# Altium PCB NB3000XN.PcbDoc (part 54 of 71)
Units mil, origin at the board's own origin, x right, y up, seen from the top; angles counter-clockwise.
Board outline 9527.56 x 6929.77 mil, 6 copper layers (Top Layer, GND+SHIELD, MidLayer1, MidLayer2, P2 - 3V3+5V0, Bottom Layer), stack 62.375 mil thick; 832 components, 1027 nets, 4655 pads, 4981 vias.
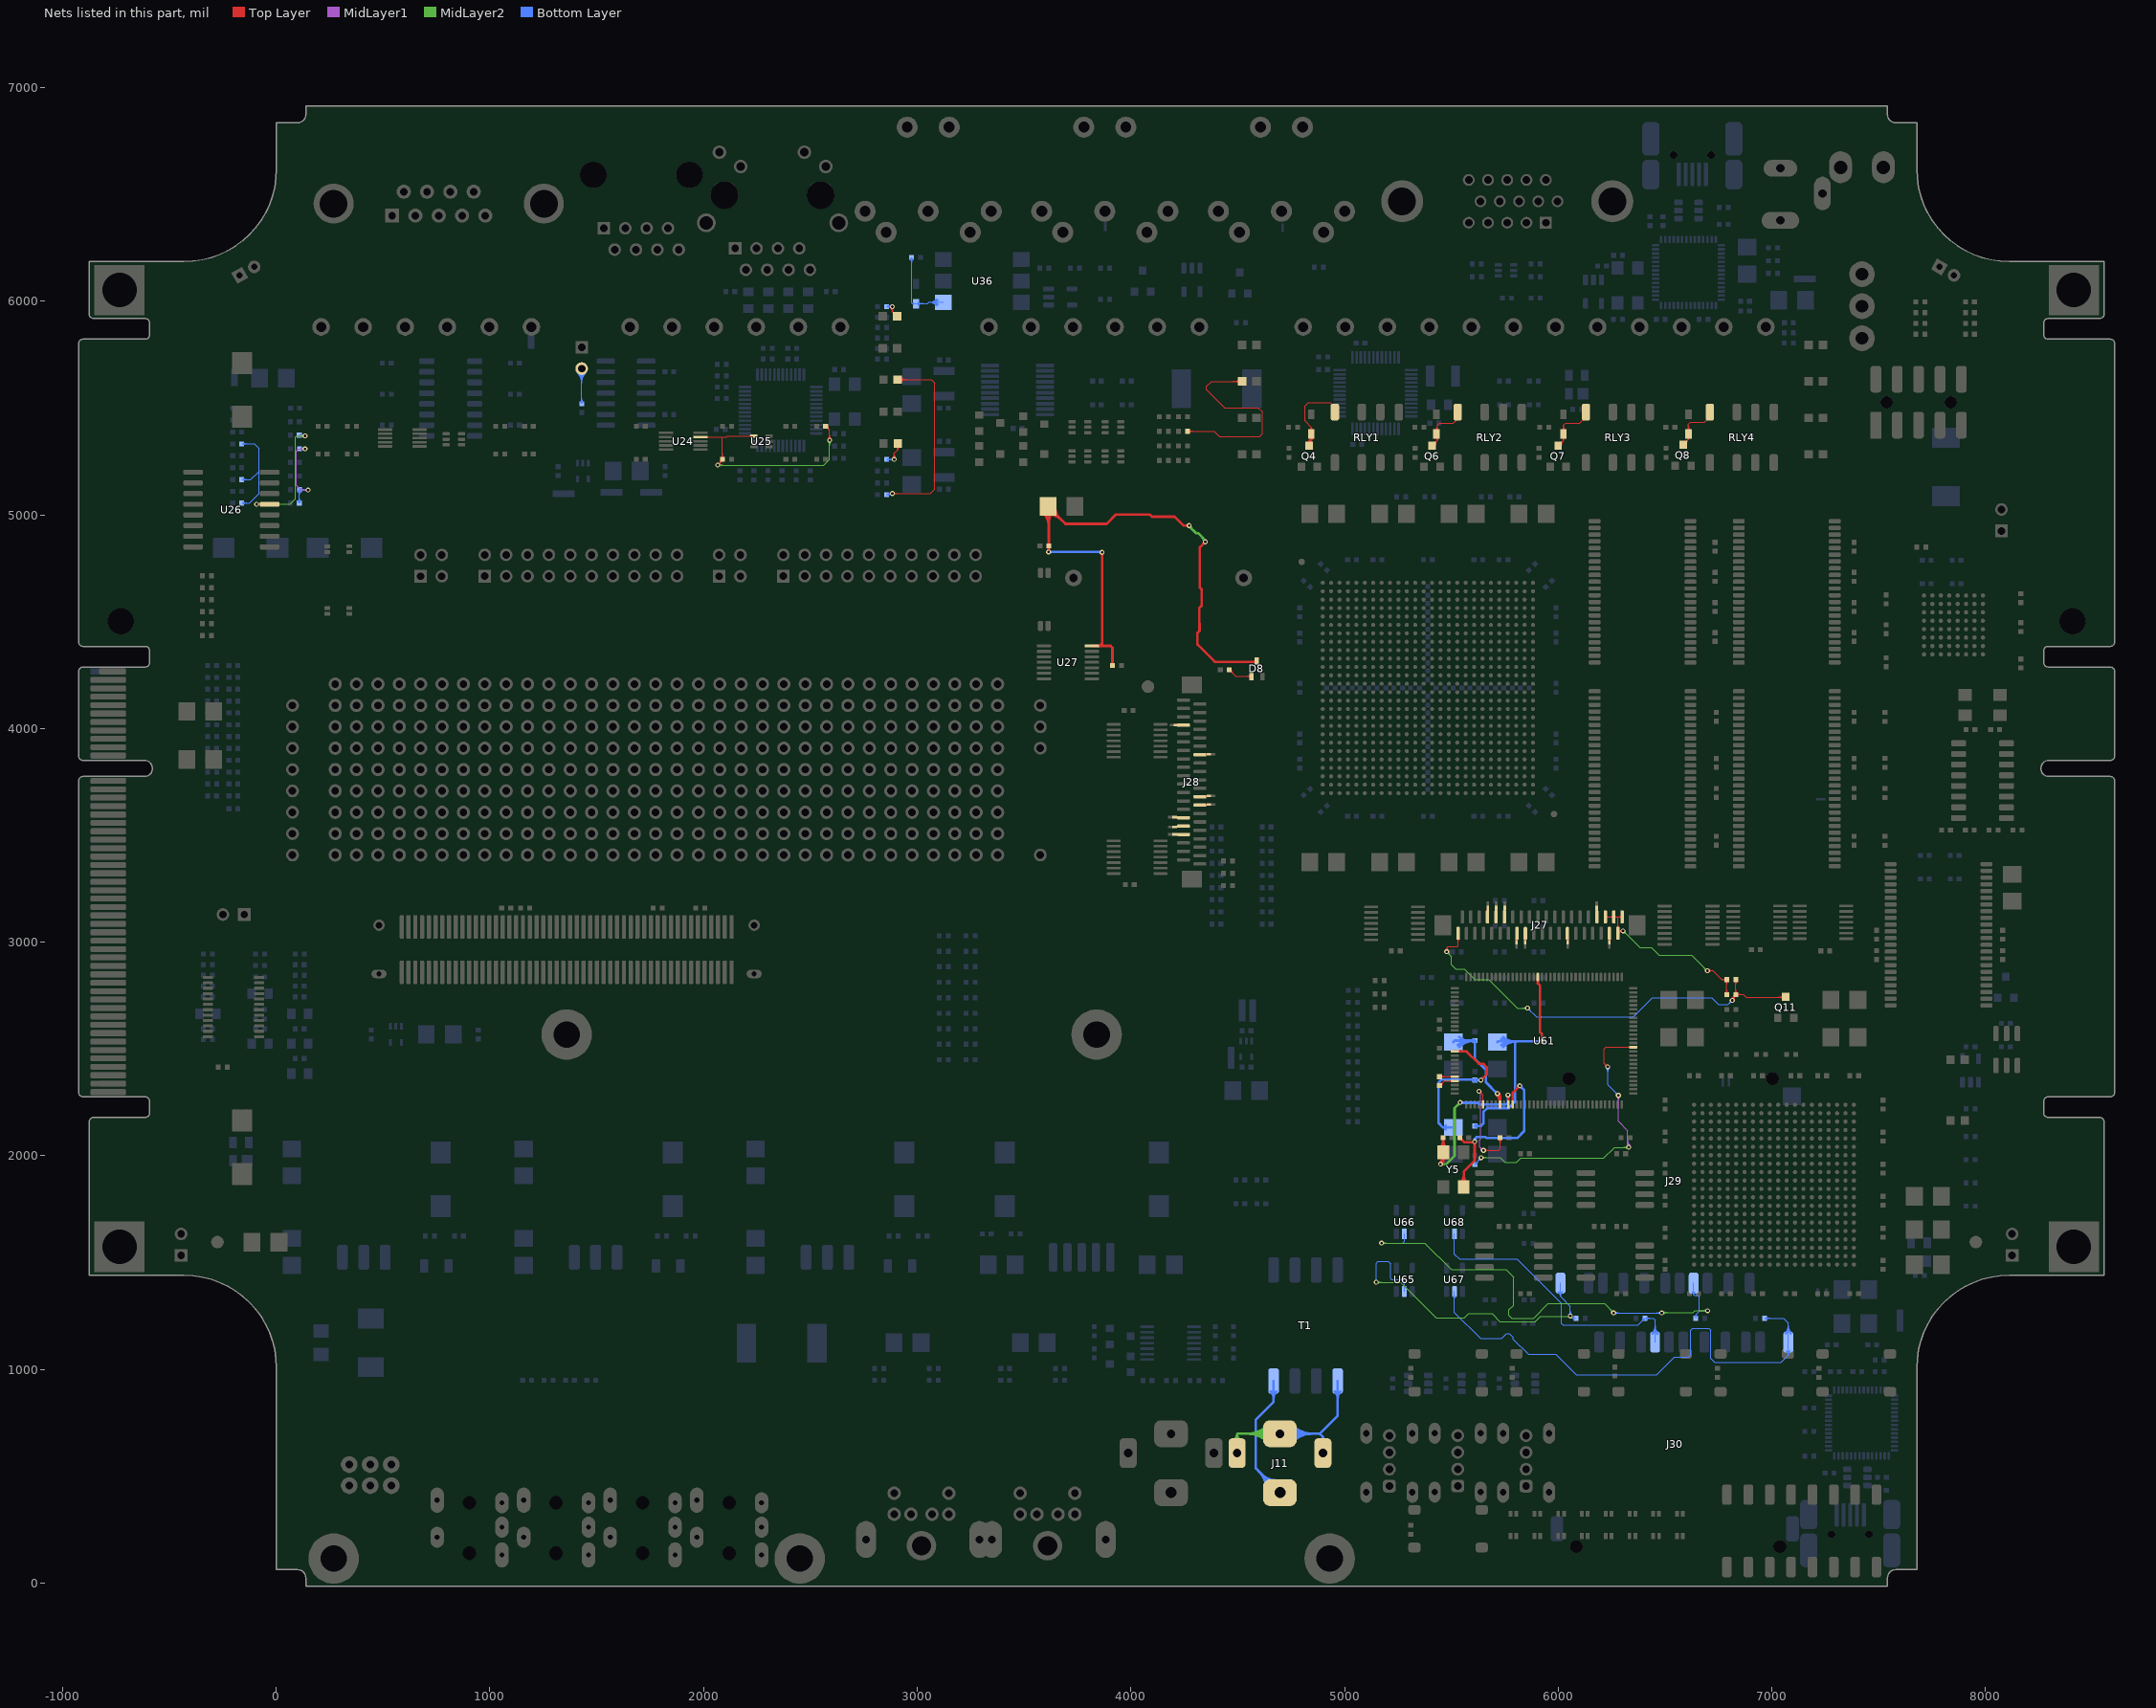
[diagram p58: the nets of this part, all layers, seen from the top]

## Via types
v1: diameter 23, hole 11.81, Top Layer to Bottom Layer, 3672 vias
v2: diameter 26, hole 11.81, Top Layer to Bottom Layer, 461 vias
v3: diameter 19, hole 11.81, Top Layer to Bottom Layer, tented both sides, 396 vias
v4: diameter 23.62, hole 11.81, Top Layer to Bottom Layer, 288 vias
v5: diameter 20, hole 11.81, Top Layer to Bottom Layer, 91 vias
v6: diameter 23, hole 11.81, Top Layer to Bottom Layer, tented both sides, 50 vias
v7: diameter 31, hole 11.81, Top Layer to Bottom Layer, 15 vias
v8: diameter 27.56, hole 11.81, Top Layer to Bottom Layer, tented both sides, 4 vias
v9: diameter 29, hole 11.81, Top Layer to Bottom Layer, 3 vias
v10: diameter 21, hole 11.81, Top Layer to Bottom Layer, 1 vias

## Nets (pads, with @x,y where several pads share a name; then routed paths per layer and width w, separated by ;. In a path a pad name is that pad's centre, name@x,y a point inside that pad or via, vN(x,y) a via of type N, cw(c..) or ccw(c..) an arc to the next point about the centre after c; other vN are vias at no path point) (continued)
NetC104_1: C104.1 R136.2 U24.4 U25.1 | length 1519
  Top Layer w4: U24.4@1985.71,5364.68 2089.69,5364.68 ; U24.4@2016,5361.86 cw(c2022.83,5355.03) 2022.83,5364.68 cw(c2022.83,5374.34) U24.4@2016,5367.51 ; v1(2066.19,5233.37) 2089.68,5256.87 R136.2@2089.68,5260 2087.19,5262.5 2087.19,5362.19 2089.69,5364.68 ; v1@2066.19,5238.87 ccw(c2066.19,5252.15) 2075.58,5242.76 ccw(c2084.97,5233.37) v1@2071.69,5233.37 ; v1@2066.19,5242.87 ccw(c2066.19,5265.81) 2082.41,5249.59 ccw(c2098.63,5233.37) v1@2075.69,5233.37 ; v1@2071.91,5239.1 ccw(c2051.5,5259.51) R136.2@2080.37,5259.51 ; 2078.28,5245.47 cw(c2089.68,5234.06) R136.2@2089.68,5250.19 ; 2078.74,5245.92 ccw(c2065.16,5259.51) R136.2@2084.37,5259.51 ; R136.2@2083.1,5267.08 ccw(c2073.21,5276.96) 2087.19,5276.96 ; 2087.19,5279.36 ccw(c2108.55,5279.36) R136.2@2093.45,5264.25 ; 2087.19,5289.02 ccw(c2118.21,5289.02) R136.2@2096.27,5267.08 ; U25.1@2221.99,5365.85 ccw(c2211.96,5355.82) 2211.96,5370 ccw(c2211.96,5384.18) U25.1@2221.99,5374.15 ; U25.1@2235,5370 2112.17,5370 2106.86,5364.68 2089.69,5364.68 ; C104.1@2571.54,5405.19 cw(c2571.53,5381.5) 2588.28,5398.25 cw(c2605.03,5415) C104.1@2581.35,5415 ; C104.1@2571.54,5409.19 cw(c2571.53,5395.16) 2581.45,5405.08 cw(c2591.38,5415) C104.1@2577.35,5415 ; C104.1@2571.54,5415 2590.19,5396.34 v1(2590.19,5350.04) ; v1@2583.47,5356.76 ccw(c2567.26,5372.98) 2590.19,5372.98 ccw(c2613.13,5372.98) v1@2596.91,5356.76 ; v1@2586.3,5353.93 ccw(c2576.91,5363.32) 2590.19,5363.32 ccw(c2603.47,5363.32) v1@2594.08,5353.93
  MidLayer2 w4: v1(2066.19,5233.37) 2535,5233.37 2563.37,5233.37 2590.19,5260.19 v1(2590.19,5350.04) ; v1@2070.08,5229.49 cw(c2079.47,5220.1) 2079.47,5233.37 cw(c2079.47,5246.65) v1@2070.08,5237.26 ; v1@2072.91,5226.66 cw(c2089.13,5210.44) 2089.13,5233.37 cw(c2089.13,5256.31) v1@2072.91,5240.09 ; v1@2583.47,5343.32 cw(c2567.26,5327.11) 2590.19,5327.11 cw(c2613.13,5327.11) v1@2596.91,5343.32 ; v1@2586.3,5346.15 cw(c2576.91,5336.76) 2590.19,5336.76 cw(c2603.47,5336.76) v1@2594.08,5346.15
NetC108_1: C108.1 U26.13 | length 913.3
  Top Layer w4: v1(-91.81,5050.04) -76.48,5050.04 ; v1@-88.12,5050.04 cw(c-88.12,5026.22) U26.13@-71.27,5043.06 ; v1@-87.92,5050.04 ccw(c-87.92,5073.59) U26.13@-71.27,5056.94 ; -78.46,5050.04 cw(c-78.46,5035.87) U26.13@-68.44,5045.89 ; -78.26,5050.04 ccw(c-78.26,5063.93) U26.13@-68.44,5054.11 ; U26.13@-73.93,5052.03 cw(c-76.43,5052.56) -76.43,5050 ; U26.13@-73.91,5052.1 cw(c-76.48,5052.66) -76.48,5050.04 ; U26.13@-30.87,5050 -76.43,5050 ; -76.48,5050.04 cw(c-76.48,5047.44) -73.93,5047.98 ccw(c-76.43,5047.44) -76.43,5050 ; -76.48,5050.04 -76.43,5050
  MidLayer2 w4: v1(-91.81,5050.04) 65.19,5050.04 90.19,5075.04 90.19,5365 95.19,5370 v1(135,5370) v1@135,5370.15 ; v1@-87.92,5046.15 cw(c-78.53,5036.76) -78.53,5050.04 cw(c-78.53,5063.32) v1@-87.92,5053.93 ; v1@-85.09,5043.32 cw(c-68.87,5027.11) -68.87,5050.04 cw(c-68.87,5072.98) v1@-85.09,5056.76 ; v1@128.28,5363.28 ccw(c112.06,5347.06) 112.06,5370 ccw(c112.06,5392.93) v1@128.28,5376.72 ; v1@131.11,5366.11 ccw(c121.72,5356.72) 121.72,5370 ccw(c121.72,5383.28) v1@131.11,5373.89
  Bottom Layer w4: C108.1@112.24,5368.83 cw(c122.16,5358.91) 122.16,5372.94 cw(c122.16,5386.97) C108.1@112.24,5377.05 ; C108.1@115.07,5366 cw(c131.81,5349.25) 131.81,5372.94 cw(c131.81,5396.62) C108.1@115.07,5379.88 ; C108.1@116.77,5372.94 cw(c116.77,5354.53) v1@130.81,5366.44 ; C108.1@119.16,5372.94 ccw(c119.16,5385.84) v1@128.28,5376.72 ; v1@127.76,5363.85 ccw(c108.13,5347.2) C108.1@108.13,5372.94 132.06,5372.94 v1(135,5370) v1@135,5370.15
NetC109_2: C109.2 R143.2 R146.1 | length 799.1
  MidLayer1 w4: v1@128.28,5302.65 ccw(c112.06,5286.43) 112.06,5309.37 ccw(c112.06,5332.3) v1@128.28,5316.09 ; v1@131.11,5305.48 ccw(c121.72,5296.09) 121.72,5309.37 ccw(c121.72,5322.65) v1@131.11,5313.26 ; v1(135,5309.37) 104.37,5309.37 95,5300 95,5138.65 116.94,5116.71 v1(149.52,5116.71) v1@151.52,5116.71 ; v1@142.81,5109.99 ccw(c126.59,5093.77) 126.59,5116.71 ccw(c126.59,5139.64) v1@142.81,5123.43 ; v1@145.64,5112.82 ccw(c136.25,5103.43) 136.25,5116.71 ccw(c136.25,5129.99) v1@145.64,5120.6
  Bottom Layer w4: C109.2@101.19,5062.02 ccw(c84.44,5078.77) 108.13,5078.77 ccw(c131.81,5078.77) C109.2@115.07,5062.02 ; R143.2@102.05,5111.57 cw(c86.14,5095.66) 108.64,5095.66 cw(c131.14,5095.66) R143.2@115.23,5111.57 ; C109.2@104.02,5059.19 ccw(c94.1,5069.11) 108.13,5069.11 ccw(c122.16,5069.11) C109.2@112.24,5059.19 ; R143.2@104.88,5114.4 cw(c95.8,5105.32) 108.64,5105.32 cw(c121.48,5105.32) R143.2@112.4,5114.4 ; C109.2@108.13,5055.08 108.13,5083.37 108.64,5083.89 R143.2@108.64,5118.65 135.52,5118.65 137.47,5116.71 v1(149.52,5116.71) ; R146.1@108.64,5309.37 v1(135,5309.37) ; R143.2@112.4,5114.89 cw(c121.48,5105.81) 121.48,5118.65 cw(c121.48,5131.5) R143.2@112.4,5122.41 ; R146.1@112.4,5305.61 cw(c121.48,5296.53) 121.48,5309.37 cw(c121.48,5322.21) R146.1@112.4,5313.13 ; R143.2@115.23,5112.06 cw(c131.14,5096.16) 131.14,5118.65 cw(c131.14,5141.15) R143.2@115.23,5125.24 ; R146.1@115.23,5302.78 cw(c131.14,5286.87) 131.14,5309.37 cw(c131.14,5331.86) R146.1@115.23,5315.96 ; v1@128.28,5302.65 ccw(c112.06,5286.43) 112.06,5309.37 ccw(c112.06,5332.3) v1@128.28,5316.09 ; v1@131.11,5305.48 ccw(c121.72,5296.09) 121.72,5309.37 ccw(c121.72,5322.65) v1@131.11,5313.26
NetC110_1: C110.1 R144.2 R145.2 | length 666
  Bottom Layer w4: C110.1@-161.36,5055.08 -124.92,5055.08 -80.81,5099.19 -80.81,5204.19 ; R145.2@-160.85,5165.08 -119.92,5165.08 -80.81,5204.19 ; R144.2@-160.85,5332.58 -102.58,5332.58 -80.81,5310.81 -80.81,5204.19 ; C110.1@-157.25,5050.97 cw(c-147.33,5041.05) -147.33,5055.08 cw(c-147.33,5069.11) C110.1@-157.25,5059.19 ; R145.2@-157.09,5161.32 cw(c-148.01,5152.24) -148.01,5165.08 cw(c-148.01,5177.92) R145.2@-157.09,5168.84 ; R144.2@-157.09,5328.82 cw(c-148.01,5319.74) -148.01,5332.58 cw(c-148.01,5345.42) R144.2@-157.09,5336.34 ; C110.1@-154.42,5048.14 cw(c-137.67,5031.4) -137.67,5055.08 cw(c-137.67,5078.77) C110.1@-154.42,5062.02 ; R145.2@-154.26,5158.49 cw(c-138.35,5142.58) -138.35,5165.08 cw(c-138.35,5187.58) R145.2@-154.26,5171.67 ; R144.2@-154.26,5325.99 cw(c-138.35,5310.08) -138.35,5332.58 cw(c-138.35,5355.08) R144.2@-154.26,5339.17
NetC115_1: C115.1 C116.1 D8.3 R148.1 U27.14 | length 3427.9
  Top Layer w4: C116.1@3615.19,4854.52 C116.1@3615.67,4855
  Top Layer w12: C115.1@3588.41,5012.47 cw(c3522.61,4946.66) 3615.67,4946.66 ; C115.1@3596.9,5020.95 cw(c3551.58,4975.63) 3615.67,4975.63 ; v1@3611.3,4830.6 ccw(c3600.76,4841.14) 3615.67,4841.14 ; C116.1@3611.56,4850.89 cw(c3601.64,4840.97) 3615.67,4840.97 cw(c3629.7,4840.97) C116.1@3619.78,4850.89 ; C116.1@3611.56,4859.11 ccw(c3601.64,4869.03) 3615.67,4869.03 ccw(c3629.7,4869.03) C116.1@3619.78,4859.11 ; C116.1@3612.01,4858.66 C116.1@3615.67,4855 ; C115.1@3612.01,5002.69 cw(c3612.01,4912.63) 3675.7,4976.31 ; C115.1@3612.01,5014.69 cw(c3612.01,4953.6) 3655.21,4996.8 ; C115.1@3612.01,5040 C115.1@3615.67,5036.34 ; v1@3615.67,4827.19 C116.1@3615.67,4855 ; 3615.67,4838.83 ccw(c3627.31,4838.83) v1@3619.08,4830.6 ; 3615.67,4964.34 cw(c3683.73,4964.34) C115.1@3635.6,5012.47 ; 3615.67,4993.31 cw(c3654.76,4993.31) C115.1@3627.12,5020.95 ; C115.1@3633.38,5036.06 ccw(c3675.47,5036.06) C115.1@3645.71,5006.3 ; C115.1@3645.38,5036.06 ccw(c3716.44,5036.06) 3666.19,4985.82 ; U27.14@3817.2,4386.77 3853.63,4386.77 ; U27.14@3843.78,4387.66 ccw(c3843.78,4413.59) 3862.11,4395.26 ; v1@3861.3,4821.15 cw(c3851.91,4811.76) 3865.19,4811.76 cw(c3878.47,4811.76) v1@3869.08,4821.15 ; v1(3865.19,4825.04) 3865.19,4398.33 3853.63,4386.77 ; R148.1@3910.06,4299.25 ccw(c3900.98,4308.33) 3913.82,4308.33 ccw(c3926.66,4308.33) R148.1@3917.58,4299.25 ; R148.1@3913.82,4295 3913.82,4378.77 3905.82,4386.77 3853.63,4386.77 ; v1@4268.97,4946.15 ccw(c4259.58,4936.76) 4259.58,4950.04 ccw(c4259.58,4963.32) v1@4268.97,4953.93 ; v1(4272.86,4950.04) 4246.67,4950.04 4205,4991.71 4099.14,4991.71 4089.03,5001.81 3930.28,5001.81 3886.96,4958.5 3693.51,4958.5 C115.1@3615.67,5036.34 ; v1@4343.02,4874.37 cw(c4329.75,4874.37) 4339.14,4864.99 cw(c4348.52,4855.6) v1@4348.52,4868.87 ; v1(4348.52,4874.37) 4323.02,4848.87 4323.02,4660.47 4331.5,4651.99 4331.5,4574.78 4320,4563.28 4320,4492.3 4321.5,4490.8 4321.5,4457.99 4312.02,4448.51 4312.02,4392.84 4392.65,4312.21 4586.78,4312.21 D8.3@4590,4315.43 ; 4572.57,4312.21 ccw(c4572.57,4332.87) D8.3@4587.17,4318.26 ; C116.1@3615.67,4855 C115.1@3615.67,5036.34
  MidLayer2 w12: v1(4272.86,4950.04) 4272.86,4946.8 4304.63,4915.02 4313.95,4915.02 4348.52,4880.45 v1(4348.52,4874.37) ; v1@4278.36,4950.04 ccw(c4299.46,4950.04) 4284.54,4935.12 ; 4334.84,4894.13 cw(c4315.09,4874.37) v1@4343.02,4874.37
  Bottom Layer w12: v1(3615.19,4826.71) v1@3863.52,4826.71 ; v1@3619.08,4822.82 cw(c3628.47,4813.43) 3628.47,4826.71 cw(c3628.47,4839.99) v1@3619.08,4830.6 ; 3847.89,4826.71 cw(c3847.89,4807.74) v1@3861.3,4821.15
NetC157_2: C157.2 U61.11 Y5.1 | length 1098.4
  Top Layer w12: v1@5445.64,1965.26 ccw(c5407.74,2003.16) Y5.1@5461.33,2003.16 ; Y5.1@5447.3,2035.7 ccw(c5413.42,2069.58) 5461.33,2069.58 ; v1(5449.52,1961.37) 5461.33,1973.18 ; Y5.1@5450.07,1994.96 cw(c5434.61,1973.17) 5461.33,1973.17 ; v1@5454.12,1956.78 ccw(c5436.71,1974.19) 5461.33,1974.19 ; C157.2@5457.22,2080.89 cw(c5447.3,2070.97) 5461.33,2070.97 cw(c5475.36,2070.97) C157.2@5465.44,2080.89 ; C157.2@5461.33,2075.23 ccw(c5517.23,2075.23) Y5.1@5477.7,2035.7 ; C157.2@5461.33,2085 5461.33,1973.18 ; Y5.1@5473.28,1993.9 ccw(c5485.29,1973.17) 5461.33,1973.17 ; v1@5761.11,2281.11 cw(c5747.26,2267.26) 5766.85,2267.26 ; v1(5765,2285) 5766.85,2283.15 U61.11@5766.85,2240
  MidLayer2 w12: v1(5449.52,1961.37) 5476.37,1961.37 5515.19,2000.19 5515.19,2223.71 v1(5541.52,2250.04) ; v1@5453.41,1957.49 cw(c5462.8,1948.1) 5462.8,1961.37 cw(c5462.8,1974.65) v1@5453.41,1965.26 ; v1@5536.02,2250.04 cw(c5522.75,2250.04) 5532.14,2240.65 cw(c5541.52,2231.26) v1@5541.52,2244.54
  Bottom Layer w12: v1(5541.52,2250.04) 5543.38,2248.19 5625,2248.19 5633.3,2239.89 5729.04,2239.89 5754.89,2239.89 5765,2250 v1(5765,2285) v1@5770.9,2285 ; v1@5545.41,2253.93 ccw(c5559.27,2267.79) 5559.27,2248.19 ; v1@5761.11,2281.11 cw(c5751.72,2271.72) 5765,2271.72 cw(c5778.28,2271.72) v1@5768.89,2281.11
NetC169_2: C169.2 U61.12 Y5.3 | length 1095.6
  Top Layer w12: C169.2@5539.33,2079.19 cw(c5539.33,2065.16) 5549.25,2075.08 cw(c5559.17,2085) C169.2@5545.14,2085 ; C169.2@5539.33,2085 5561.14,2063.19 5606,2063.19 v1(5609.19,2066.37) 5609.19,1977.37 5559.1,1927.29 5559.1,1855.1 Y5.3@5557.5,1853.5 ; Y5.3@5542.3,1872.7 ccw(c5501.73,1913.27) 5559.1,1913.27 ; 5559.1,1905.54 ccw(c5605.54,1905.54) Y5.3@5572.7,1872.7 ; v1@5605.3,2062.49 cw(c5595.91,2053.1) 5609.19,2053.1 cw(c5622.47,2053.1) v1@5613.08,2062.49 ; U61.12@5786.53,2240 5786.53,2273.8 5787.73,2275 5787.73,2295.92 v1(5820.19,2328.37) ; v1@5814.69,2328.37 cw(c5801.41,2328.37) 5810.8,2318.99 cw(c5820.19,2309.6) v1@5820.19,2322.87
  Bottom Layer w12: v1(5609.19,2066.37) 5609.19,2079.19 5618.21,2088.21 ; v1@5614.27,2068.48 cw(c5631.02,2075.39) 5618.21,2088.21 ; v1@5820.19,2322.87 cw(c5820.19,2309.6) 5829.58,2318.99 cw(c5838.97,2328.37) v1@5825.69,2328.37 ; v1@5826.63,2328.37 v1(5820.19,2328.37) 5840.69,2307.87 5840.69,2115.19 5808.87,2083.37 5664.26,2083.37 5659.43,2088.21 5618.21,2088.21
NetC186_1: C186.1 U61.124 | length 146.3
  Top Layer w4: C186.1@5445,2370.67 5473.52,2370.67 5473.57,2370.72 U61.124@5516.83,2370.72 ; C186.1@5449.11,2366.56 cw(c5459.03,2356.64) 5459.03,2370.67 cw(c5459.03,2384.7) C186.1@5449.11,2374.78 ; C186.1@5451.94,2363.73 cw(c5468.68,2346.98) 5468.68,2370.67 cw(c5468.69,2394.36) C186.1@5451.94,2377.61 ; U61.124@5500.81,2367.89 ccw(c5493.98,2361.06) 5493.98,2370.72 ccw(c5493.98,2380.37) U61.124@5500.81,2373.54
NetC186_2: C186.2 U61.125 | length 155.2
  Top Layer w4: C186.2@5445,2329.33 5466.7,2351.03 U61.125@5516.83,2351.03 ; C186.2@5445,2335.14 ccw(c5445,2349.17) 5454.92,2339.25 ccw(c5464.84,2329.33) C186.2@5450.81,2329.33 ; C186.2@5445,2339.14 ccw(c5445,2362.83) 5461.75,2346.08 ; C186.2@5454.81,2329.33 cw(c5478.5,2329.33) 5461.75,2346.08 ; U61.125@5500.81,2348.2 ccw(c5493.98,2341.37) 5493.98,2351.03 ccw(c5493.98,2360.69) U61.125@5500.81,2353.86
NetC187_1: C187.1 U61.5 | length 743.4
  Top Layer w4: v1@5629.18,2292.81 cw(c5629.18,2269.88) 5645.4,2286.09 cw(c5661.62,2302.31) v1@5638.68,2302.31 ; v1@5629.18,2296.81 cw(c5629.18,2283.53) 5638.57,2292.92 cw(c5647.96,2302.31) v1@5634.68,2302.31 ; v1(5629.18,2302.31) 5648.74,2282.75 U61.5@5648.74,2240 ; U61.5@5645.91,2256.02 ccw(c5639.08,2262.85) 5648.74,2262.85 ccw(c5658.4,2262.85) U61.5@5651.57,2256.02 ; v4(5650,2025) 5720,2025 5728.08,2033.08 C187.1@5728.08,2085 ; v4@5654.11,2020.89 cw(c5664.03,2010.97) 5664.03,2025 cw(c5664.03,2039.03) v4@5654.11,2029.11 ; v4@5656.94,2018.06 cw(c5673.69,2001.31) 5673.69,2025 cw(c5673.69,2048.69) v4@5656.94,2031.94 ; C187.1@5721.14,2078.06 cw(c5704.39,2061.31) 5728.08,2061.31 cw(c5751.76,2061.31) C187.1@5735.01,2078.06 ; C187.1@5723.97,2080.89 cw(c5714.05,2070.97) 5728.08,2070.97 cw(c5742.1,2070.97) C187.1@5732.18,2080.89
  MidLayer1 w4: v1(5629.18,2302.31) 5637.81,2293.68 5637.81,2078.74 5633.02,2073.96 5633.02,2041.98 v4(5650,2025) ; v4@5640.19,2025 ccw(c5616.5,2025) 5633.25,2041.75 ccw(c5650,2058.5) v4@5650,2034.81 ; v4@5644.19,2025 ccw(c5630.16,2025) 5640.08,2034.92 ccw(c5650,2044.84) v4@5650,2030.81
NetC336_1: C336.1 C340.1 U61.9 | length 763.6
  Top Layer w12: v1@5711.3,2287.82 cw(c5672.24,2248.76) U61.9@5727.48,2248.76 ; v1(5715.19,2291.71) 5727.48,2279.42 U61.9@5727.48,2240 ; v1@5719.79,2296.3 cw(c5701.21,2277.73) 5727.48,2277.73
  Bottom Layer w12: C340.1@5510,2532.99 5516.34,2539.33 C336.1@5610,2539.33 5610,2455.3 5661.69,2403.61 5661.69,2345.21 v1(5715.19,2291.71) ; C340.1@5529.05,2517.88 cw(c5580.83,2466.1) 5580.83,2539.33 ; C340.1@5537.53,2509.4 cw(c5609.8,2437.13) C336.1@5609.8,2539.33 ; C340.1@5537.53,2556.59 ccw(c5579.2,2598.25) 5579.2,2539.33 ; C336.1@5605.89,2543.44 cw(c5595.97,2553.36) 5595.97,2539.33 cw(c5595.97,2525.3) 5605.89,2535.22 cw(c5595.97,2525.3) 5610,2525.3 cw(c5624.03,2525.3) C336.1@5614.11,2535.22 ; v1@5709.69,2291.71 ccw(c5696.41,2291.71) 5705.8,2301.1 ccw(c5715.19,2310.49) v1@5715.19,2297.21
NetC337_1: C337.1 C341.1 U61.118 | length 839.3
  Top Layer w12: U61.118@5516.83,2488.83 5571.17,2488.83 5628.63,2431.37 5648.63,2431.37 5665.19,2414.81 5665.19,2381.37 v1(5638.19,2354.37) ; v1@5638.19,2359.87 ccw(c5638.19,2373.15) 5647.58,2363.76 ccw(c5656.97,2354.37) v1@5643.69,2354.37
  Bottom Layer w4: v1@5638.15,2354.33 v1(5638.19,2354.37)
  Bottom Layer w12: C341.1@5473.94,2123.95 ccw(c5462.01,2120.6) 5462.01,2132.99 ; C341.1@5473.94,2142.03 cw(c5462.01,2145.39) 5462.01,2132.99 ; C341.1@5510,2132.99 5462.01,2132.99 ; 5587.99,2357.64 cw(c5587.99,2332.32) C337.1@5605.89,2350.22 ; C337.1@5614.11,2350.22 cw(c5624.03,2340.3) 5624.03,2354.33 cw(c5624.03,2368.36) C337.1@5614.11,2358.44 ; 5624.81,2354.33 ccw(c5624.81,2367.76) v1@5634.3,2358.26 ; 5625.02,2354.33 cw(c5625.02,2341.2) v1@5634.3,2350.49 ; v1@5638.15,2354.33 C337.1@5610,2354.33 5606.69,2357.64 5454.49,2357.64 5440,2343.14 5440,2155 5462.01,2132.99
NetC338_1: C338.1 C342.1 U61.85 | length 1340
  Top Layer w12: U61.85@5904.65,2837.34 5904.65,2807.4 5915.19,2796.85 5915.19,2580 5923.52,2571.67 v1(5923.52,2535.71) ; v1@5919.64,2539.6 ccw(c5910.25,2548.99) 5923.52,2548.99 ccw(c5936.8,2548.99) v1@5927.41,2539.6
  Bottom Layer w12: C338.1@5610,2139.33 5637.14,2139.33 5650,2152.19 5650,2205 5668.89,2223.89 5768.89,2223.89 5797.69,2252.69 5797.69,2528.4 5805,2535.71 ; C338.1@5614.11,2135.22 cw(c5624.03,2125.3) 5624.03,2139.33 cw(c5624.03,2153.36) C338.1@5614.11,2143.44 ; C342.1@5715,2532.99 5717.72,2535.71 5805,2535.71 ; C342.1@5734.05,2548.1 ccw(c5763.97,2578.03) 5763.97,2535.71 ; C342.1@5734.18,2518.01 cw(c5776.38,2476.54) 5776.38,2535.71 ; C342.1@5742.53,2556.59 ccw(c5792.94,2607) 5792.94,2535.71 ; C342.1@5742.74,2509.6 cw(c5805,2448.42) 5805,2535.71 ; v1@5919.64,2531.82 ccw(c5910.25,2522.43) 5910.25,2535.71 ccw(c5910.25,2548.99) v1@5919.64,2539.6 ; v1(5923.52,2535.71) 5805,2535.71
NetC339_1: C339.1 U61.50 | length 1969
  Top Layer w4: v1@6222.36,2416.71 ccw(c6199.42,2416.71) 6215.64,2432.93 ccw(c6231.86,2449.14) v1@6231.86,2426.21 ; v1@6226.36,2416.71 ccw(c6213.08,2416.71) 6222.47,2426.1 ccw(c6231.86,2435.49) v1@6231.86,2422.21 ; v1(6231.86,2416.71) 6215.19,2433.37 6215.19,2500.04 6223.66,2508.51 U61.50@6351.93,2508.51 ; U61.50@6335.91,2505.68 ccw(c6329.08,2498.85) 6329.08,2508.51 ccw(c6329.08,2518.17) U61.50@6335.91,2511.34
  MidLayer1 w4: v1@6275.14,2276.66 cw(c6258.92,2260.44) 6281.86,2260.44 cw(c6304.79,2260.44) v1@6288.57,2276.66 ; v1@6277.97,2279.49 cw(c6268.58,2270.1) 6281.86,2270.1 cw(c6295.14,2270.1) v1@6285.75,2279.49 ; v1(6281.86,2283.37) 6281.86,2161.63 6325,2118.48 6325,2040 v4(6330,2040) ; v4@6323.06,2046.94 ccw(c6318.39,2051.61) 6325,2051.61 ; 6325,2056.44 ccw(c6346.44,2056.44) v4@6331.28,2041.28 ; 6325,2066.1 ccw(c6356.1,2066.1) v4@6334.11,2044.11 ; 6325,2075.76 ccw(c6365.76,2075.76) v4@6336.94,2046.94
  MidLayer2 w4: v1(5639.52,1991.71) 5729.23,1991.71 5750.4,1970.54 5805.77,1970.54 5825.23,1990 6213.23,1990 6263.23,2040 v4(6330,2040) ; v1@5643.41,1987.82 cw(c5652.8,1978.43) 5652.8,1991.71 cw(c5652.8,2004.99) v1@5643.41,1995.6 ; v1@5646.24,1984.99 cw(c5662.46,1968.77) 5662.46,1991.71 cw(c5662.46,2014.64) v1@5646.24,1998.43 ; v4@6323.06,2033.06 ccw(c6306.31,2016.31) 6306.31,2040 ccw(c6306.31,2063.69) v4@6323.06,2046.94 ; v4@6325.89,2035.89 ccw(c6315.97,2025.97) 6315.97,2040 ccw(c6315.97,2054.03) v4@6325.89,2044.11
  Bottom Layer w4: C339.1@5610,1959.33 v1@5639.52,1988.85 ; C339.1@5610,1965.14 ccw(c5610,1979.17) 5619.92,1969.25 ccw(c5629.84,1959.33) C339.1@5615.81,1959.33 ; C339.1@5610,1969.14 ccw(c5610,1992.83) 5626.75,1976.08 ; C339.1@5619.81,1959.33 cw(c5643.5,1959.33) 5626.75,1976.08 ; C339.1@5621.29,1970.62 ccw(c5600.2,1991.71) v1@5630.02,1991.71 ; 5628.12,1977.45 ccw(c5613.86,1991.71) v1@5634.02,1991.71 ; 5628.18,1977.51 cw(c5639.52,1966.16) v1@5639.52,1982.21 ; v1@6225.14,2409.99 cw(c6208.92,2393.77) 6231.86,2393.77 cw(c6254.79,2393.77) v1@6238.57,2409.99 ; v1@6227.97,2412.82 cw(c6218.58,2403.43) 6231.86,2403.43 cw(c6245.14,2403.43) v1@6235.75,2412.82 ; v1(6231.86,2416.71) 6231.86,2333.37 v1(6281.86,2283.37) ; v1@6272.36,2283.37 ccw(c6249.42,2283.37) 6265.64,2299.59 ccw(c6281.86,2315.81) v1@6281.86,2292.87 ; v1@6276.36,2283.37 ccw(c6263.08,2283.37) 6272.47,2292.76 ccw(c6281.86,2302.15) v1@6281.86,2288.87
NetD3_1: D3.1 Q4.2 RLY1.8 | length 744
  Top Layer w4: Q4.2@4825.18,5337.46 ccw(c4792.13,5378.74) D3.1@4845,5378.74 ; Q4.2@4827.68,5334.34 ccw(c4798.79,5370.41) D3.1@4845,5370.41 ; Q4.2@4830.18,5331.22 ccw(c4805.46,5362.08) D3.1@4845,5362.08 ; Q4.2@4832.68,5328.1 ccw(c4812.13,5353.75) 4845,5353.75 ; Q4.2@4835,5324.21 4845,5334.21 D3.1@4845,5378.74 ; Q4.2@4835.18,5324.98 ccw(c4818.8,5345.43) 4845,5345.43 ; D3.1@4835.81,5362.05 cw(c4813.62,5339.85) 4845,5339.85 cw(c4876.39,5339.85) D3.1@4854.19,5362.05 ; D3.1@4837.92,5397.14 ccw(c4829.44,5410.19) 4845,5410.19 ; D3.1@4838.64,5364.88 cw(c4823.27,5349.51) 4845,5349.51 cw(c4866.73,5349.51) D3.1@4851.36,5364.88 ; D3.1@4840.1,5393.79 ccw(c4834.23,5402.82) 4845,5402.82 ccw(c4855.77,5402.82) D3.1@4849.9,5393.79 ; D3.1@4852.08,5397.14 cw(c4860.56,5410.19) 4845,5410.19 ; 4937.64,5522.36 cw(c4925.38,5510.11) RLY1.8@4941.93,5504.97 ; 4939.47,5520.53 ccw(c4953.86,5534.91) RLY1.8@4954.54,5514.58 ; RLY1.8@4942.32,5517.68 cw(c4932.53,5507.89) RLY1.8@4945.75,5503.78 ; RLY1.8@4955,5481.22 4955,5505 4935,5525 4830,5525 4815,5510 4815,5440.19 4845,5410.19 ; D3.1@4845,5378.74 4845,5410.19
NetD4_1: D4.1 Q6.2 RLY2.8 | length 455.9
  Top Layer w4: Q6.2@5410.51,5324.72 5435,5349.21 ; Q6.2@5410.76,5332.88 ccw(c5412.27,5348.05) Q6.2@5423.05,5337.27 ; Q6.2@5411.16,5336.86 ccw(c5413.35,5358.91) 5429.03,5343.24 ; Q6.2@5411.56,5340.84 ccw(c5414.43,5369.78) 5435,5349.21 ; Q6.2@5421.71,5325.58 cw(c5444.83,5326.33) 5428.47,5342.69 ; D4.1@5422.76,5397.03 ccw(c5407.35,5420) 5435,5420 ; D4.1@5424.99,5393.71 ccw(c5412.38,5412.5) 5435,5412.5 ; Q6.2@5425.71,5325.71 cw(c5457.47,5326.74) 5435,5349.21 ; D4.1@5427.1,5358.57 cw(c5424.83,5348.65) 5435,5348.65 ; D4.1@5427.21,5390.39 ccw(c5417.41,5404.99) 5435,5404.99 ; D4.1@5427.99,5362.47 cw(c5425.98,5353.67) 5435,5353.67 ; 5435,5351.93 cw(c5449.31,5351.93) D4.1@5439.19,5362.05 ; D4.1@5435,5370 5435,5349.21 ; D4.1@5435,5373.74 5435,5420 ; 5435,5405.55 ccw(c5449.31,5405.55) D4.1@5439.19,5395.43 ; RLY2.8@5535,5476.22 5535,5455 5510,5430 5445,5430 5435,5420
NetD5_1: D5.1 Q7.2 RLY3.8 | length 477.2
  Top Layer w4: Q7.2@6000.51,5324.72 6025,5349.21 ; Q7.2@6000.76,5332.88 ccw(c6002.27,5348.05) Q7.2@6013.05,5337.27 ; Q7.2@6001.16,5336.86 ccw(c6003.35,5358.91) 6019.03,5343.24 ; Q7.2@6001.56,5340.84 ccw(c6004.43,5369.78) 6025,5349.21 ; Q7.2@6011.71,5325.58 cw(c6034.83,5326.33) 6018.47,5342.69 ; Q7.2@6015.71,5325.71 cw(c6047.47,5326.74) 6025,5349.21 ; D5.1@6015.81,5395.43 ccw(c5993.62,5417.62) 6025,5417.62 ccw(c6056.39,5417.62) D5.1@6034.19,5395.43 ; D5.1@6018.64,5392.6 ccw(c6003.27,5407.97) 6025,5407.97 ccw(c6046.73,5407.97) D5.1@6031.36,5392.6 ; D5.1@6018.72,5359.86 cw(c6012.84,5349.21) 6025,5349.21 ; D5.1@6020.65,5363.36 cw(c6016.58,5355.99) 6025,5355.99 cw(c6033.42,5355.99) D5.1@6029.35,5363.36 ; D5.1@6025,5370 6025,5349.21 ; D5.1@6025,5373.74 6025,5420 6035,5430 6100,5430 6125,5455 RLY3.8@6125,5476.22 ; D5.1@6031.28,5359.86 ccw(c6037.16,5349.21) 6025,5349.21
  Top Layer w12: RLY3.8@6123.82,5475.04 RLY3.8@6130,5481.22
NetD6_1: D6.1 Q8.2 RLY4.8 | length 440.8
  Top Layer w4: Q8.2@6585,5329.21 Q8.2@6586.02,5329.21 ; Q8.2@6585.51,5329.72 6610,5354.21 ; Q8.2@6585.76,5337.88 ccw(c6587.27,5353.05) Q8.2@6598.05,5342.27 ; Q8.2@6586.16,5341.86 ccw(c6588.35,5363.91) 6604.03,5348.24 ; Q8.2@6586.56,5345.84 ccw(c6589.43,5374.78) 6610,5354.21 ; Q8.2@6596.71,5330.58 cw(c6619.83,5331.33) 6603.47,5347.69 ; Q8.2@6600.71,5330.71 cw(c6632.47,5331.74) 6610,5354.21 ; D6.1@6600.81,5395.43 ccw(c6578.62,5417.62) 6610,5417.62 ccw(c6641.39,5417.62) D6.1@6619.19,5395.43 ; D6.1@6603.64,5392.6 ccw(c6588.27,5407.97) 6610,5407.97 ccw(c6631.73,5407.97) D6.1@6616.36,5392.6 ; D6.1@6606.58,5358.7 cw(c6605.35,5354.21) 6610,5354.21 ; D6.1@6610,5375 6610,5354.21 ; D6.1@6610,5378.74 6610,5425 6620,5435 6685,5435 6710,5460 RLY4.8@6710,5481.22 ; D6.1@6613.43,5358.7 ccw(c6614.65,5354.21) 6610,5354.21
  Top Layer w12: RLY4.8@6707.85,5483.37 RLY4.8@6710,5481.22
NetD8_1: D8.1 R147.2 | length 201.7
  Top Layer w4: R147.2@4461.18,4265.19 cw(c4461.18,4241.5) 4477.93,4258.25 ; R147.2@4461.18,4269.19 cw(c4461.18,4255.16) R147.2@4471.1,4265.08 ; R147.2@4461.18,4275 4491.61,4244.57 D8.1@4564.41,4244.57 ; R147.2@4466.5,4274.51 ccw(c4478.15,4274.51) R147.2@4469.91,4266.27 ; R147.2@4470.5,4274.51 ccw(c4491.81,4274.51) 4476.74,4259.44 ; D8.1@4558.75,4238.91 ccw(c4545.1,4225.25) 4545.1,4244.57 ccw(c4545.1,4263.88) D8.1@4558.75,4250.22
NetD9_2: D9.2 R194.1 U36.1 | length 794.7
  Bottom Layer w4: R194.1@2967.23,6197.92 cw(c2951.32,6182.01) 2973.82,6182.01 cw(c2996.32,6182.01) R194.1@2980.41,6197.92 ; R194.1@2970.06,6200.75 cw(c2960.98,6191.67) 2973.82,6191.67 cw(c2986.66,6191.67) R194.1@2977.58,6200.75 ; R194.1@2973.82,6205 2973.82,5991.41 2976.49,5988.74 ; D9.2@2982.77,5984.33 ccw(c2976.49,5982.05) 2976.49,5988.74 ; D9.2@2982.77,5993.15 cw(c2976.49,5995.42) 2976.49,5988.74 ; D9.2@3001.36,5982.38 cw(c3016.73,5967.01) 3016.73,5988.74 cw(c3016.73,6010.47) D9.2@3001.36,5995.1 ; D9.2@3004.19,5979.55 cw(c3026.38,5957.36) 3026.38,5988.74 cw(c3026.39,6020.13) D9.2@3004.19,5997.93 ; U36.1@3090.33,5976.3 ccw(c3054.79,5951.87) 3054.79,5995 ; U36.1@3090.33,6013.69 cw(c3054.79,6038.13) 3054.79,5995 ; U36.1@3093.62,5978.57 ccw(c3062.39,5957.1) 3062.39,5995 ccw(c3062.39,6032.9) U36.1@3093.62,6011.43 ; U36.1@3096.92,5980.84 ccw(c3069.99,5962.33) 3069.99,5995 ccw(c3069.99,6027.67) U36.1@3096.92,6009.16 ; U36.1@3100.21,5983.1 ccw(c3077.6,5967.55) 3077.6,5995 ccw(c3077.6,6022.44) U36.1@3100.21,6006.9 ; U36.1@3122.52,5995 3054.78,5995 ; 2976.49,5988.74 D9.2@2995,5988.74 3048.52,5988.74 3054.78,5995
NetJ11_1: J11.1 T1.8 | length 1076
  Bottom Layer w12: 4597.03,524.75 cw(c4499.86,427.58) J11.1@4637.25,424.74 ; 4611.82,509.96 ccw(c4682.23,580.37) J11.1@4682.23,480.79 ; 4616.93,504.85 cw(c4538.85,426.78) J11.1@4649.25,424.49 ; 4632.31,489.47 ccw(c4682.23,539.4) J11.1@4682.23,468.79 ; 4636.83,484.95 cw(c4577.84,425.97) J11.1@4661.24,424.24 ; T1.8@4654.56,897.45 cw(c4622.13,865.01) 4668,865.01 cw(c4713.87,865.01) T1.8@4681.44,897.45 ; T1.8@4668,945.92 4668,848 4585,765 4585,536.78 J11.1@4697.98,423.8
NetJ11_2: J11.2 J11.3 J11.4 T1.5 | length 2056.1
  MidLayer2 w12: J11.3@4480.43,668.42 ccw(c4464.13,697.19) 4497.19,697.19 ; J11.3@4497.19,608.84 4497.19,697.19 ; J11.3@4513.95,668.42 cw(c4530.26,697.19) 4497.19,697.19 ; J11.4@4641.93,659.09 ccw(c4544.64,561.8) 4544.64,699.39 ccw(c4544.64,836.98) J11.4@4641.93,739.69 ; J11.4@4650.42,667.58 ccw(c4573.61,590.77) 4573.61,699.39 ccw(c4573.61,808.01) J11.4@4650.42,731.21 ; J11.4@4658.9,676.06 ccw(c4602.58,619.74) 4602.58,699.39 ccw(c4602.58,779.04) J11.4@4658.9,722.72 ; J11.4@4697.98,699.39 4499.39,699.39 4497.19,697.19
  Bottom Layer w12: J11.4@4697.98,699.39 4884.39,699.39 ; J11.4@4737.06,676.06 cw(c4793.38,619.74) 4793.38,699.39 cw(c4793.38,779.04) J11.4@4737.06,722.72 ; J11.4@4745.54,667.58 cw(c4822.35,590.77) 4822.35,699.39 cw(c4822.35,808.01) J11.4@4745.54,731.21 ; J11.4@4754.03,659.09 cw(c4851.32,561.8) 4851.32,699.39 cw(c4851.32,836.98) J11.4@4754.03,739.69 ; J11.2@4888.67,671.31 ccw(c4884.41,685.02) 4898.77,685.02 ; J11.2@4898.77,608.84 4898.77,685.02 ; J11.2@4908.86,671.31 cw(c4913.12,685.02) 4898.77,685.02 ; T1.5@4954.56,897.45 cw(c4922.13,865.01) 4968,865.01 cw(c5013.87,865.01) T1.5@4981.44,897.45 ; T1.5@4968,945.92 4968,783 4884.39,699.39 ; 4884.39,699.39 4898.77,685.02
NetJ26_2: J26.2 R212.2 | length 545.6
  Bottom Layer w4: J26.2@1410.24,5665.16 cw(c1363.25,5618.16) 1429.71,5618.16 cw(c1496.16,5618.17) J26.2@1449.17,5665.16 ; J26.2@1413.07,5667.99 cw(c1372.91,5627.82) 1429.71,5627.82 cw(c1486.51,5627.82) J26.2@1446.35,5667.99 ; J26.2@1415.9,5670.81 cw(c1382.56,5637.48) 1429.71,5637.48 cw(c1476.85,5637.48) J26.2@1443.52,5670.81 ; J26.2@1418.73,5673.64 cw(c1392.22,5647.13) 1429.71,5647.13 cw(c1467.19,5647.14) J26.2@1440.69,5673.64 ; R212.2@1423.41,5527.77 ccw(c1407.5,5543.68) 1430,5543.68 ccw(c1452.5,5543.68) R212.2@1436.59,5527.77 ; R212.2@1426.24,5524.94 ccw(c1417.16,5534.02) 1430,5534.02 ccw(c1442.84,5534.02) R212.2@1433.76,5524.94 ; J26.2@1429.71,5684.62 1429.71,5600.33 1430,5600.04 R212.2@1430,5521.18
NetJ27_1: J27.1 J27.2 J27.3 J27.5 R100.1 R101.1 | length 1338.2
  Top Layer w4: J27.5@6220.54,3118.39 J27.3@6259.91,3118.39 6280,3118.39 ; J27.5@6224.69,3114.23 cw(c6234.72,3104.2) 6234.72,3118.39 cw(c6234.72,3132.57) J27.5@6224.69,3122.54 ; J27.3@6255.75,3114.23 ccw(c6245.73,3104.2) 6245.73,3118.39 ccw(c6245.73,3132.57) J27.3@6255.75,3122.54 ; J27.3@6264.06,3114.23 cw(c6274.09,3104.2) 6274.09,3118.39 cw(c6274.09,3132.57) J27.3@6264.06,3122.54 ; J27.2@6275.44,3067.89 ccw(c6265.41,3077.92) 6279.59,3077.92 ccw(c6293.77,3077.92) J27.2@6283.75,3067.89 ; J27.2@6278.56,3040.58 cw(c6297,3022.14) v1@6302.39,3047.66 ; J27.2@6283.78,3045.8 cw(c6298.82,3030.76) v1@6303.21,3051.57 ; 6289,3051.02 cw(c6300.64,3039.37) v1@6304.04,3055.49 ; J27.1@6295.12,3114.23 ccw(c6285.1,3104.2) 6285.1,3118.39 ccw(c6285.1,3132.57) J27.1@6295.12,3122.54 ; J27.1@6299.28,3118.39 6280,3118.39 ; v1(6303.52,3053.04) 6291.02,3053.04 J27.2@6279.59,3041.61 6279.59,3117.98 6280,3118.39 ; v1(6698.52,2866.71) 6723.52,2866.71 6765.23,2825 6788.33,2825 6788.57,2824.75 R100.1@6788.82,2824.51 ; v1@6702.41,2862.82 cw(c6711.8,2853.43) 6711.8,2866.71 cw(c6711.8,2879.99) v1@6702.41,2870.6 ; v1@6705.24,2859.99 cw(c6721.46,2843.77) 6721.46,2866.71 cw(c6721.46,2889.64) v1@6705.24,2873.43 ; R101.1@6782.23,2762.08 ccw(c6766.32,2777.99) 6788.82,2777.99 ccw(c6811.32,2777.99) R101.1@6795.41,2762.08 ; R100.1@6782.23,2817.92 cw(c6766.32,2802.01) 6788.82,2802.01 cw(c6811.32,2802.01) R100.1@6795.41,2817.92 ; R100.1@6782.23,2818.41 ccw(c6766.32,2802.5) 6766.32,2825 ccw(c6766.32,2847.5) R100.1@6782.23,2831.59 ; R101.1@6785.06,2759.25 ccw(c6775.98,2768.33) 6788.82,2768.33 ccw(c6801.66,2768.33) R101.1@6792.58,2759.25 ; R100.1@6785.06,2820.75 cw(c6775.98,2811.67) 6788.82,2811.67 cw(c6801.66,2811.67) R100.1@6792.58,2820.75 ; R100.1@6785.06,2821.24 ccw(c6775.98,2812.16) 6775.98,2825 ccw(c6775.98,2837.84) R100.1@6785.06,2828.76 ; R101.1@6788.82,2755 R100.1@6788.82,2824.51 ; R100.1@6788.82,2825 R100.1@6788.82,2824.51
  MidLayer2 w4: v1@6303.52,3043.54 cw(c6303.52,3020.61) 6319.74,3036.82 cw(c6335.96,3053.04) v1@6313.02,3053.04 ; v1@6303.52,3047.54 cw(c6303.52,3034.26) 6312.91,3043.65 cw(c6322.3,3053.04) v1@6309.02,3053.04 ; v1(6303.52,3053.04) 6381.86,2974.71 6435.63,2974.71 6462.44,2947.9 6471.96,2938.37 6624.19,2938.37 v1@6695.86,2866.71 ; 6677.75,2884.81 ccw(c6698.52,2905.58) v1@6698.52,2876.21 ; 6684.19,2878.37 cw(c6672.53,2866.71) v1@6689.02,2866.71 ; 6684.58,2877.98 ccw(c6698.52,2891.92) v1@6698.52,2872.21
NetJ27_4: J27.4 NT34.1 | length 79.2
  Top Layer w4: J27.4@6236.07,3015.33 cw(c6226.04,3005.31) 6240.22,3005.31 cw(c6254.4,3005.31) J27.4@6244.38,3015.33 ; NT34.1@6237.17,3007.33 ccw(c6229.81,3014.69) J27.4@6240.22,3014.69 ; NT34.1@6240,3000 6240.22,3000.22 J27.4@6240.22,3041.61 ; J27.4@6240.22,3013.62 ccw(c6249.12,3013.62) NT34.1@6242.83,3007.33
NetJ27_7: J27.7 NT39.1 | length 79.5
  Top Layer w4: J27.7@6177.01,3144.67 ccw(c6166.98,3154.69) 6181.17,3154.69 ccw(c6195.35,3154.69) J27.7@6185.32,3144.67 ; NT39.1@6177.17,3152.67 cw(c6167.52,3143.02) J27.7@6181.17,3143.02 ; NT39.1@6180,3160 6181.17,3158.83 J27.7@6181.17,3118.39 ; 6181.17,3148.66 cw(c6186.84,3148.66) NT39.1@6182.83,3152.67
NetJ27_14: J27.14 NT38.1 | length 76.5
  Top Layer w4: J27.14@6039.22,3015.33 cw(c6029.19,3005.31) 6043.37,3005.31 cw(c6057.55,3005.31) J27.14@6047.53,3015.33 ; J27.14@6043.37,3017.59 ccw(c6058.59,3017.59) NT38.1@6047.83,3006.83 ; J27.14@6043.37,3041.61 6043.37,3001.63 NT38.1@6045,3000
NetJ27_24: J27.24 NT37.1 | length 79.7
  Top Layer w4: NT37.1@5842.17,3007.33 ccw(c5831.67,3017.83) J27.24@5846.52,3017.83 ; J27.24@5842.37,3015.33 cw(c5832.34,3005.31) 5846.52,3005.31 cw(c5860.7,3005.31) J27.24@5850.68,3015.33 ; NT37.1@5845,3000 5846.52,3001.52 J27.24@5846.52,3041.61 ; NT37.1@5846.52,3010.48 ccw(c5850.98,3010.48) NT37.1@5847.83,3007.33
NetJ27_26: J27.26 NT41.1 | length 78.1
  Top Layer w4: NT41.1@5802.17,3007.33 ccw(c5790.15,3019.35) J27.26@5807.15,3019.35 ; J27.26@5803,3015.33 cw(c5792.97,3005.31) 5807.15,3005.31 cw(c5821.33,3005.31) J27.26@5811.31,3015.33 ; NT41.1@5805,3000 5807.15,3002.15 J27.26@5807.15,3041.61
NetJ27_29: J27.29 NT35.1 | length 77.4
  Top Layer w4: J27.29@5743.94,3144.67 ccw(c5733.92,3154.69) 5748.1,3154.69 ccw(c5762.28,3154.69) J27.29@5752.25,3144.67 ; J27.29@5748.1,3118.39 5748.1,3158.1 NT35.1@5750,3160 ; J27.29@5748.1,3141.25 cw(c5764.25,3141.25) NT35.1@5752.83,3152.67
NetJ27_31: J27.31 NT36.1 | length 79.6
  Top Layer w4: J27.31@5704.57,3144.67 ccw(c5694.55,3154.69) 5708.73,3154.69 ccw(c5722.91,3154.69) J27.31@5712.88,3144.67 ; NT36.1@5707.17,3152.67 cw(c5703.42,3148.92) 5708.73,3148.92 ; J27.31@5708.73,3118.39 5708.73,3158.73 NT36.1@5710,3160 ; J27.31@5708.73,3142.77 cw(c5722.73,3142.77) NT36.1@5712.83,3152.67
NetJ27_33: J27.33 NT40.1 | length 79.3
  Top Layer w4: J27.33@5665.2,3144.67 ccw(c5655.18,3154.69) 5669.36,3154.69 ccw(c5683.54,3154.69) J27.33@5673.51,3144.67 ; NT40.1@5667.17,3152.67 cw(c5661.9,3147.4) J27.33@5669.36,3147.4 ; J27.33@5669.36,3118.39 5669.36,3159.36 NT40.1@5670,3160 ; J27.33@5669.36,3144.29 cw(c5681.21,3144.29) NT40.1@5672.83,3152.67
NetJ27_40: J27.40 Q11.2 R100.2 R101.2 | length 2749
  Top Layer w4: v4@5473.42,2964.43 ccw(c5468.22,2975) 5480,2975 ; v4@5475.18,2960.84 ccw(c5471.38,2968.58) 5480,2968.58 ; v4(5477.74,2955.62) 5477.74,2952.17 5479.96,2949.96 5480,2950 5480,2975 5485,2980 5528,2980 5531.56,2983.56 5531.56,3000 ; 5480,2973.86 ccw(c5495.99,2973.86) v4@5484.68,2962.56 ; J27.40@5527.41,3015.33 cw(c5517.38,3005.31) 5531.56,3005.31 cw(c5545.74,3005.31) J27.40@5535.71,3015.33 ; 5531.56,2988.04 5531.56,3000 ; J27.40@5531.56,3041.61 5531.56,3000 ; v1@6812.77,2727.08 cw(c6825.99,2730.5) 6816.33,2740.15 ; v1@6814.94,2738.76 cw(c6830.48,2723.23) R101.2@6830.97,2745.19 ; v1(6815.19,2727.71) 6815.19,2739.01 R101.2@6831.18,2755 6866.71,2755 6880,2741.71 7065,2741.71 Q11.2@7065,2744.21 ; 6815.62,2739.44 ccw(c6800.55,2754.51) R101.2@6821.86,2754.51 ; v1@6816.64,2728.08 cw(c6833.85,2732.53) R101.2@6821.28,2745.1 ; v1@6820.52,2729.08 cw(c6841.72,2734.57) R101.2@6826.23,2750.05 ; R101.2@6821.56,2745.38 cw(c6830.77,2736.17) R101.2@6831.06,2749.19 ; R101.2@6822.45,2746.27 ccw(c6814.21,2754.51) R101.2@6825.86,2754.51 ; v1@6824.39,2730.09 cw(c6849.58,2736.6) R101.2@6831.18,2755 ; R101.2@6824.59,2762.08 ccw(c6808.68,2777.99) 6831.18,2777.99 ccw(c6853.68,2777.99) R101.2@6837.77,2762.08 ; R100.2@6824.59,2817.92 cw(c6808.68,2802.01) 6831.18,2802.01 cw(c6853.68,2802.01) R100.2@6837.77,2817.92 ; R101.2@6827.42,2759.25 ccw(c6818.34,2768.33) 6831.18,2768.33 ccw(c6844.02,2768.33) R101.2@6834.94,2759.25 ; R100.2@6827.42,2820.75 cw(c6818.34,2811.67) 6831.18,2811.67 cw(c6844.02,2811.67) R100.2@6834.94,2820.75 ; R101.2@6831.18,2766.03 R100.2@6831.18,2825 ; R101.2@6834.94,2751.24 cw(c6844.02,2742.16) 6844.02,2755 cw(c6844.02,2767.84) R101.2@6834.94,2758.76 ; R101.2@6837.77,2748.41 cw(c6853.68,2732.5) 6853.68,2755 cw(c6853.68,2777.5) R101.2@6837.77,2761.59 ; 7023.39,2741.71 ccw(c7023.39,2784.84) Q11.2@7053.89,2754.34 ; 7030.73,2741.71 cw(c7030.73,2708.96) Q11.2@7053.89,2732.12 ; 7033.04,2741.71 ccw(c7033.04,2775.19) Q11.2@7056.72,2751.51 ; 7040.38,2741.71 cw(c7040.38,2718.61) Q11.2@7056.72,2734.94 ; 7042.7,2741.71 ccw(c7042.7,2765.53) Q11.2@7059.54,2748.68
  MidLayer2 w4: v4@5477.74,2945.81 cw(c5477.74,2922.13) 5494.49,2938.87 cw(c5511.24,2955.62) v4@5487.56,2955.62 ; v4@5477.74,2949.81 cw(c5477.74,2935.78) 5487.66,2945.7 cw(c5497.58,2955.62) v4@5483.56,2955.62 ; v4(5477.74,2955.62) 5500,2933.37 5500,2894.63 5520,2874.63 5561.29,2874.63 5610.54,2825.37 5676.19,2825.37 5809.86,2691.71 v1(5856.86,2691.71) ; v1@5850.14,2684.99 ccw(c5833.92,2668.77) 5833.92,2691.71 ccw(c5833.92,2714.64) v1@5850.14,2698.43 ; v1@5852.97,2687.82 ccw(c5843.58,2678.43) 5843.58,2691.71 ccw(c5843.58,2704.99) v1@5852.97,2695.6
  Bottom Layer w4: v1@5856.86,2682.21 cw(c5856.86,2659.27) 5873.07,2675.49 cw(c5889.29,2691.71) v1@5866.36,2691.71 ; v1@5856.86,2686.21 cw(c5856.86,2672.93) 5866.25,2682.32 cw(c5875.64,2691.71) v1@5862.36,2691.71 ; v1(5856.86,2691.71) 5898.52,2650.04 6351.19,2650.04 6440.19,2739.04 6696.84,2739.04 6719.33,2739.04 6750,2708.37 6795.86,2708.37 v1(6815.19,2727.71) ; v1@6805.69,2727.71 cw(c6782.76,2727.71) 6798.97,2711.49 cw(c6815.19,2695.27) v1@6815.19,2718.21 ; v1@6809.69,2727.71 cw(c6796.41,2727.71) 6805.8,2718.32 cw(c6815.19,2708.93) v1@6815.19,2722.21
NetJ28_7: J28.7 NT28.1 | length 87
  Top Layer w4: NT28.1@4205,4020 NT28.1@4212.08,4020 ; NT28.1@4216.58,4016.49 cw(c4225.06,4008.01) J28.7@4225.06,4020 ; NT28.1@4216.98,4020 cw(c4216.98,4014.21) J28.7@4222.65,4015.37 ; NT28.1@4218.73,4014.57 ccw(c4212.08,4013.21) NT28.1@4212.08,4020 ; NT28.1@4219.41,4013.66 cw(c4234.71,3998.35) J28.7@4234.71,4020 ; J28.7@4246.61,4015.75 4242.36,4020 NT28.1@4212.08,4020
NetJ28_14: J28.14 NT29.1 | length 88.9
  Top Layer w4: J28.14@4323.39,3877.95 4325.43,3880 NT29.1@4365,3880 ; J28.14@4346.84,3876.63 cw(c4354.98,3868.49) NT29.1@4354.98,3880 ; J28.14@4349.67,3873.8 cw(c4364.63,3858.83) NT29.1@4364.63,3880 ; J28.14@4349.67,3882.11 ccw(c4354.75,3887.19) NT29.1@4354.75,3880 ; NT29.1@4357.67,3877.17 ccw(c4350.84,3870.34) 4350.84,3880 ccw(c4350.84,3889.66) NT29.1@4357.67,3882.83
NetJ28_24: J28.24 NT33.1 | length 87.2
  Top Layer w4: J28.24@4323.39,3681.1 4327.28,3685 NT33.1@4365,3685 ccw(c4365,3666.56) J28.24@4350.22,3677.59 ; J28.24@4347.01,3679.98 cw(c4357.02,3672.51) NT33.1@4357.02,3685 ; NT33.1@4357.67,3682.17 ccw(c4350.84,3675.34) 4350.84,3685 ccw(c4350.84,3694.66) NT33.1@4357.67,3687.83
NetJ28_26: J28.26 NT30.1 | length 86.1
  Top Layer w4: J28.26@4323.39,3641.73 4326.65,3645 NT30.1@4365,3645 ccw(c4365,3625.53) J28.26@4350.03,3637.98 ; J28.26@4346.95,3640.53 cw(c4356.47,3632.62) NT30.1@4356.47,3645 ; NT30.1@4357.67,3642.17 ccw(c4350.84,3635.34) 4350.84,3645 ccw(c4350.84,3654.66) NT30.1@4357.67,3647.83
NetJ28_29: J28.29 NT26.1 | length 89.3
  Top Layer w4: NT26.1@4212.33,3582.17 cw(c4219.16,3575.34) 4219.16,3585 cw(c4219.16,3594.66) NT26.1@4212.33,3587.83 ; NT26.1@4214.51,3585 cw(c4214.51,3572.92) J28.29@4223.15,3581.37 ; 4215.91,3585 ccw(c4215.91,3591.25) J28.29@4220.33,3586.83 ; J28.29@4220.29,3578.57 ccw(c4205,3563.61) NT26.1@4205,3585 4244.29,3585 J28.29@4246.61,3582.68
NetJ28_31: J28.31 NT27.1 | length 86.1
  Top Layer w4: NT27.1@4212.33,3537.17 cw(c4219.16,3530.34) 4219.16,3540 cw(c4219.16,3549.66) NT27.1@4212.33,3542.83 ; NT27.1@4213.49,3540 ccw(c4213.49,3552.39) J28.31@4223.04,3544.5 ; J28.31@4219.96,3547.05 cw(c4205,3559.4) NT27.1@4205,3540 4243.31,3540 J28.31@4246.61,3543.31
NetJ28_33: J28.33 NT31.1 | length 79.5
  Top Layer w4: NT31.1@4205,3505 4245.55,3505 J28.33@4246.61,3503.94 ; NT31.1@4207.74,3505 cw(c4207.74,3487.19) J28.33@4220.33,3499.78 ; NT31.1@4212.33,3502.17 cw(c4219.16,3495.34) 4219.16,3505 cw(c4219.16,3514.66) NT31.1@4212.33,3507.83 ; NT31.1@4212.87,3505 ccw(c4212.87,3515.55) J28.33@4220.33,3508.09
NetJ29_CD: J29.CD R253.2 U66.2 | length 2698.9
  MidLayer2 w4: v1(5173.52,1591.71) 5375.9,1591.71 5500.56,1467.04 5756.65,1467.04 5790.52,1433.16 5790.52,1300.52 5770,1280 5770,1253.56 5783.35,1240.21 5884.75,1240.21 5952.91,1308.37 6216.63,1308.37 v4(6260,1265) ; v1@5177.41,1587.82 cw(c5186.8,1578.43) 5186.8,1591.71 cw(c5186.8,1604.99) v1@5177.41,1595.6 ; v1@5180.24,1584.99 cw(c5196.46,1568.77) 5196.46,1591.71 cw(c5196.46,1614.64) v1@5180.24,1598.43 ; v4@6250.19,1265 ccw(c6226.5,1265) 6243.25,1281.75 ccw(c6260,1298.5) v4@6260,1274.81 ; v4@6254.19,1265 ccw(c6240.16,1265) 6250.08,1274.92 ccw(c6260,1284.84) v4@6260,1270.81 ; v4(6485,1265) 6485.87,1265.87 6631.77,1265.87 6640.94,1275.04 v1(6699.52,1275.04) ; v4@6489.11,1260.89 cw(c6501.14,1248.86) 6501.14,1265.87 ; v4@6489.11,1269.11 ccw(c6496.92,1276.92) 6496.92,1265.87 ; v4@6491.94,1258.06 cw(c6510.8,1239.2) 6510.8,1265.87 ; v4@6491.94,1271.94 ccw(c6506.57,1286.57) 6506.57,1265.87 ; v1@6692.81,1268.32 ccw(c6676.59,1252.11) 6676.59,1275.04 ccw(c6676.59,1297.98) v1@6692.81,1281.76 ; v1@6695.64,1271.15 ccw(c6686.25,1261.76) 6686.25,1275.04 ccw(c6686.25,1288.32) v1@6695.64,1278.93
  Bottom Layer w4: v1(5173.52,1591.71) 5271.71,1591.71 5280,1600 U66.2@5280,1634.88 ; v4(6260,1265) v4(6485,1265) ; v4@6264.11,1260.89 cw(c6274.03,1250.97) 6274.03,1265 cw(c6274.03,1279.03) v4@6264.11,1269.11 ; v4@6266.94,1258.06 cw(c6283.69,1241.31) 6283.69,1265 cw(c6283.69,1288.69) v4@6266.94,1271.94 ; v4@6478.06,1258.06 ccw(c6461.31,1241.31) 6461.31,1265 ccw(c6461.31,1288.69) v4@6478.06,1271.94 ; v4@6480.89,1260.89 ccw(c6470.97,1250.97) 6470.97,1265 ccw(c6470.97,1279.03) v4@6480.89,1269.11 ; J29.CD@6627.71,1358.42 cw(c6624.95,1349.77) 6634.03,1349.77 ; J29.CD@6628.92,1362.23 cw(c6626.7,1355.25) 6634.03,1355.25 cw(c6641.37,1355.25) J29.CD@6639.14,1362.23 ; J29.CD@6634.03,1404.65 6634.03,1349.77 ; R253.2@6639.44,1248.72 ccw(c6635.57,1256) 6643.82,1256 ; J29.CD@6640.35,1358.42 ccw(c6643.11,1349.77) 6634.03,1349.77 ; R253.2@6643.82,1240 6643.82,1256 ; R253.2@6648.19,1248.72 cw(c6652.07,1256) 6643.82,1256 ; v1@6692.81,1268.32 ccw(c6676.59,1252.11) 6676.59,1275.04 ccw(c6676.59,1297.98) v1@6692.81,1281.76 ; v1@6695.64,1271.15 ccw(c6686.25,1261.76) 6686.25,1275.04 ccw(c6686.25,1288.32) v1@6695.64,1278.93 ; v1(6699.52,1275.04) 6660.52,1275.04 ; 6634.03,1349.77 6636.37,1347.44 6652.52,1347.44 6660.52,1339.44 6660.52,1275.04 ; 6643.82,1256 6660.52,1272.71 6660.52,1275.04
NetJ29_WP: J29.WP R254.2 U65.2 | length 1779.7
  MidLayer2 w4: v1(5148.19,1408.37) 5262.21,1408.37 5428.88,1241.71 5561.2,1241.71 5580.78,1261.29 5690.26,1261.29 5727.33,1224.21 5891.38,1224.21 5916.37,1249.21 6056.02,1249.21 v1(6056.86,1250.04) ; v1@5152.08,1404.49 cw(c5161.47,1395.1) 5161.47,1408.37 cw(c5161.47,1421.65) v1@5152.08,1412.26 ; v1@5154.91,1401.66 cw(c5171.13,1385.44) 5171.13,1408.37 cw(c5171.13,1431.31) v1@5154.91,1415.09
  Bottom Layer w4: v1(5148.19,1408.37) 5148.19,1498.19 5155,1505 5205,1505 5215,1495 5215,1425 5220,1420 5270,1420 5280,1410 U65.2@5280,1364.88 ; J29.WP@6000.49,1360.17 cw(c5990.39,1342.43) 6010.8,1342.43 ; J29.WP@6002.47,1363.65 cw(c5994.31,1349.31) 6010.8,1349.31 cw(c6027.3,1349.31) J29.WP@6019.14,1363.65 ; J29.WP@6010.8,1404.65 6010.8,1342.43 ; J29.WP@6021.12,1360.17 ccw(c6031.22,1342.43) 6010.8,1342.43 ; v1@6050.14,1256.76 ccw(c6033.92,1272.98) 6056.86,1272.98 ccw(c6079.79,1272.98) v1@6063.57,1256.76 ; v1@6052.97,1253.93 ccw(c6043.58,1263.32) 6056.86,1263.32 ccw(c6070.14,1263.32) v1@6060.75,1253.93 ; R254.2@6075.94,1235.02 ccw(c6066.9,1229.3) 6066.9,1240 ; R254.2@6075.94,1244.98 cw(c6066.9,1250.7) 6066.9,1240 ; R254.2@6083.82,1240 6066.9,1240 ; 6010.8,1342.43 6056.86,1296.37 v1(6056.86,1250.04) 6066.9,1240
NetJ30_CD: J30.CD R255.2 U68.2 | length 1646.7
  Bottom Layer w4: U68.2@5515,1634.88 5515,1540 5538.29,1516.71 5806.86,1516.71 6015.19,1308.37 6015.19,1214.34 6021.82,1207.71 6373.89,1207.71 R255.2@6406.18,1240 ; 6389.43,1223.25 cw(c6406.18,1206.5) R255.2@6406.18,1230.19 ; 6390.62,1224.44 ccw(c6375.55,1239.51) R255.2@6396.86,1239.51 ; R255.2@6396.26,1230.08 cw(c6406.18,1220.16) R255.2@6406.18,1234.19 ; R255.2@6397.45,1231.27 ccw(c6389.21,1239.51) R255.2@6400.86,1239.51 ; R255.2@6409.83,1236.35 6413.48,1240 6435,1240 6436.82,1240 6445,1240 6453.82,1231.18 J30.CD@6453.82,1128.35 ; R255.2@6409.94,1236.24 cw(c6419.02,1227.16) 6419.02,1240 cw(c6419.02,1252.84) R255.2@6409.94,1243.76 ; R255.2@6412.77,1233.41 cw(c6428.68,1217.5) 6428.68,1240 cw(c6428.68,1262.5) R255.2@6412.77,1246.59 ; J30.CD@6439.08,1169.46 ccw(c6403.52,1205.02) 6453.82,1205.02 ccw(c6504.12,1205.02) J30.CD@6468.55,1169.46 ; J30.CD@6441.91,1166.63 ccw(c6413.17,1195.37) 6453.82,1195.37 ccw(c6494.46,1195.37) J30.CD@6465.72,1166.63 ; J30.CD@6444.74,1163.8 ccw(c6422.83,1185.71) 6453.82,1185.71 ccw(c6484.8,1185.71) J30.CD@6462.89,1163.8
NetJ30_WP: J30.WP R256.2 U67.2 | length 2732.7
  Bottom Layer w4: U67.2@5509.66,1342.87 cw(c5503.28,1333.04) 5515,1333.04 cw(c5526.72,1333.04) U67.2@5520.34,1342.87 ; U67.2@5515,1364.88 5515,1266.9 5637.2,1144.69 5735.09,1144.69 5757.94,1167.54 5772.44,1167.54 5790.19,1149.79 5790.19,1141.71 5860.9,1071 5989.51,1071 6085.8,974.71 6460.54,974.71 6544.21,1058.37 6608.37,1058.37 6620,1070 6620,1182.85 6628.86,1191.71 6682,1191.71 ; 6682,1192 6706,1192 6714,1184 6714,1051.23 6731.86,1033.37 7043.37,1033.37 7077.05,1067.05 ; R256.2@6966.18,1240 7055,1240 7077.05,1217.95 J30.WP@7077.05,1128.35 7077.05,1067.05 ; R256.2@6969.94,1236.24 cw(c6979.02,1227.16) 6979.02,1240 cw(c6979.02,1252.84) R256.2@6969.94,1243.76 ; R256.2@6972.77,1233.41 cw(c6988.68,1217.5) 6988.68,1240 cw(c6988.68,1262.5) R256.2@6972.77,1246.59 ; J30.WP@7062.31,1169.46 ccw(c7026.75,1205.02) 7077.05,1205.02 ccw(c7127.34,1205.02) J30.WP@7091.78,1169.46 ; J30.WP@7065.14,1166.63 ccw(c7036.4,1195.37) 7077.05,1195.37 ccw(c7117.69,1195.37) J30.WP@7088.95,1166.63 ; J30.WP@7067.15,1083.63 cw(c7058.2,1067.05) 7077.05,1067.05 ; J30.WP@7067.97,1163.8 ccw(c7046.06,1185.71) 7077.05,1185.71 ccw(c7108.03,1185.71) J30.WP@7086.12,1163.8 ; J30.WP@7069.05,1087.15 cw(c7061.81,1073.75) 7077.05,1073.75 cw(c7092.28,1073.75) J30.WP@7085.04,1087.15 ; J30.WP@7086.94,1083.63 ccw(c7095.9,1067.05) 7077.05,1067.05
NetLED4_1: LED4.1 R62.2 | length 321.3
  Top Layer w4: v1@2876.93,5968.2 cw(c2861.96,5952.68) 2883.52,5952.68 ; v1@2879.71,5971.08 cw(c2871.04,5962.1) 2883.52,5962.1 cw(c2896.01,5962.1) v1@2887.34,5971.08 ; v1(2883.52,5975.04) 2883.52,5952.68 ; LED4.1@2888.95,5933.9 ccw(c2869.21,5938.37) 2883.52,5952.68 ; v1@2890.12,5968.2 ccw(c2905.08,5952.68) 2883.52,5952.68 ; LED4.1@2892.86,5933.02 ccw(c2877.58,5936.48) 2888.65,5947.55 ccw(c2899.73,5958.63) LED4.1@2903.18,5943.35 ; LED4.1@2902.3,5947.25 cw(c2897.84,5966.99) 2883.52,5952.68 ; LED4.1@2906.2,5930 2883.52,5952.68
  Bottom Layer w4: R62.2@2856.18,5975 2883.48,5975 v1(2883.52,5975.04) ; R62.2@2859.94,5971.24 cw(c2869.02,5962.16) 2869.02,5975 cw(c2869.02,5987.84) R62.2@2859.94,5978.76 ; R62.2@2860.49,5975 ccw(c2860.49,5998.07) v1@2876.81,5981.76 ; R62.2@2860.69,5975 cw(c2860.69,5952.2) v1@2876.81,5968.32 ; R62.2@2862.77,5968.41 cw(c2878.68,5952.5) 2878.68,5975 cw(c2878.68,5997.5) R62.2@2862.77,5981.59 ; 2870.15,5975 ccw(c2870.15,5988.42) v1@2879.64,5978.93 ; 2870.34,5975 cw(c2870.34,5961.86) v1@2879.64,5971.15
NetLED5_1: LED5.1 R63.2 | length 1239.6
  Top Layer w4: v1(2883.52,5100.04) 3062.23,5100.04 3082.19,5120 3082.19,5617.81 3066.74,5633.26 LED5.1@2909.01,5633.26 ; v1@2887.41,5096.15 cw(c2896.8,5086.76) 2896.8,5100.04 cw(c2896.8,5113.32) v1@2887.41,5103.93 ; v1@2890.24,5093.32 cw(c2906.46,5077.11) 2906.46,5100.04 cw(c2906.46,5122.98) v1@2890.24,5106.76 ; LED5.1@2915.86,5626.41 cw(c2932.39,5609.88) 2932.39,5633.26 cw(c2932.39,5656.64) LED5.1@2915.86,5640.11 ; LED5.1@2918.69,5623.59 cw(c2942.05,5600.22) 2942.05,5633.26 cw(c2942.05,5666.3) LED5.1@2918.69,5642.94 ; LED5.1@2921.52,5620.76 cw(c2951.71,5590.57) 2951.71,5633.26 cw(c2951.71,5675.96) LED5.1@2921.52,5645.77
  Bottom Layer w4: R63.2@2859.97,5091.26 cw(c2868.91,5082.43) 2868.91,5095 cw(c2868.91,5107.57) R63.2@2859.97,5098.74 ; R63.2@2862.81,5088.45 cw(c2878.48,5072.98) v1@2878.48,5095 ; R63.2@2862.81,5101.55 ccw(c2878.48,5117.02) v1@2878.48,5095 ; R63.2@2863.7,5095 ccw(c2863.7,5113.4) v1@2878.96,5103.12 ; 2871.22,5095 ccw(c2871.22,5108.33) v1@2882.28,5100.88 ; 2872.76,5095 cw(c2872.76,5089.28) v1@2876.81,5093.32 ; v1@2875.65,5105.35 cw(c2856.18,5118.48) R63.2@2856.18,5095 v1@2878.48,5095 ; v1(2883.52,5100.04) v1@2878.48,5095
NetLED7_1: LED7.1 R67.2 | length 343.6
  Top Layer w4: v1@2885.81,5266.76 ccw(c2869.59,5282.98) 2892.52,5282.98 ccw(c2915.46,5282.98) v1@2899.24,5266.76 ; v1@2888.64,5263.93 ccw(c2879.25,5273.32) 2892.52,5273.32 ccw(c2905.8,5273.32) v1@2896.41,5263.93 ; v1(2892.52,5260.04) 2892.52,5288.29 2909.07,5304.83 ; LED7.1@2901.03,5317.96 cw(c2894.33,5304.83) 2909.07,5304.83 ; LED7.1@2902.85,5321.52 cw(c2897.66,5311.36) 2909.07,5311.36 cw(c2920.47,5311.36) LED7.1@2915.29,5321.52 ; LED7.1@2909.07,5333.71 2909.07,5304.83 ; LED7.1@2917.11,5317.96 ccw(c2923.81,5304.83) 2909.07,5304.83
  Bottom Layer w4: R67.2@2856.18,5260 2892.48,5260 v1(2892.52,5260.04) ; R67.2@2859.94,5256.24 cw(c2869.02,5247.16) 2869.02,5260 cw(c2869.02,5272.84) R67.2@2859.94,5263.76 ; R67.2@2862.77,5253.41 cw(c2878.68,5237.5) 2878.68,5260 cw(c2878.68,5282.5) R67.2@2862.77,5266.59 ; 2869.49,5260 ccw(c2869.49,5283.07) v1@2885.81,5266.76 ; 2869.69,5260 cw(c2869.69,5237.2) v1@2885.81,5253.32 ; 2879.15,5260 ccw(c2879.15,5273.42) v1@2888.64,5263.93 ; 2879.34,5260 cw(c2879.34,5246.86) v1@2888.64,5256.15
NetLED8_2: LED8.2 R91.2 | length 1174.5
  Top Layer w4: R91.2@4266.18,5391.67 4390.19,5391.67 4415.15,5366.71 4602.57,5366.71 4615.52,5379.67 4615.52,5482.43 4595.96,5502 4438.48,5502 4354.02,5586.46 4354.02,5600.96 4377.97,5624.9 LED8.2@4520.49,5624.9 ; R91.2@4269.94,5387.91 cw(c4279.02,5378.83) 4279.02,5391.67 cw(c4279.02,5404.51) R91.2@4269.94,5395.43 ; R91.2@4272.77,5385.08 cw(c4288.68,5369.17) 4288.68,5391.67 cw(c4288.68,5414.16) R91.2@4272.77,5398.26 ; LED8.2@4507.98,5612.4 ccw(c4477.79,5582.21) 4477.79,5624.9 ccw(c4477.79,5667.6) LED8.2@4507.98,5637.41 ; LED8.2@4510.81,5615.23 ccw(c4487.45,5591.87) 4487.45,5624.9 ccw(c4487.45,5657.94) LED8.2@4510.81,5634.58 ; LED8.2@4513.64,5618.06 ccw(c4497.1,5601.52) 4497.1,5624.9 ccw(c4497.1,5648.29) LED8.2@4513.64,5631.75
